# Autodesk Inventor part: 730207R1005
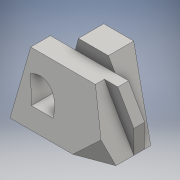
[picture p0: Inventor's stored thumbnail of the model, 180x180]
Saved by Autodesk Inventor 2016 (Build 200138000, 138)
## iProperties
Created: 2023-02
Part Number: 730207R1005
Material: 일반
Document SubType Name: Modeling
Designer: PC-1-18
Density: 1 g/cm^3
Appearance: 기본값
Author: PC-1-18
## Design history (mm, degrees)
sketch "스케치1"
  geometry: L1 (-52.5, -22.5)-(52.5, -22.5); L2 (52.5, -22.5)-(52.5, 22.5); L3 (52.5, 22.5)-(-52.5, 22.5); L4 (-52.5, 22.5)-(-52.5, -22.5); L5 (-52.5, -22.5)-(52.5, 22.5); L6 (52.5, -22.5)-(-52.5, 22.5); 1 further point
  constraints: 12 end point, 2 midpoint, 2 parallel, 1 horizontal, 1 perpendicular
  dimensions: "d0" = 105 distance of L2.end L3.end; "d1" = 45 distance of L1.end L2.end
extrude "돌출1" new body sketch "스케치1" distance "d2" = 57; taper "d3" = 0 deg
sketch "스케치2"
  geometry: L1 (0, 0)-(0, 45) reference; L2 (0, 45)-(-57, 45) reference; L3 (-57, 0)-(-57, 45) reference; L4 (0, 0)-(-57, 0) reference; L5 (0, 0)-(0, 45) reference; L6 (0, 0)-(-57, 23.029); L7 (-57, 0)-(-57, 23.029); L8 (-57, 0)-(-57, 45) reference; L9 (-57, 0)-(0, 0); 1 further point
  constraints: 6 end point, 1 collinear, 1 perpendicular, 1 point on line
  dimensions: "d4" = 68 deg angle of L1 L6
extrude "돌출2" cut sketch "스케치2" stored distance "d5" = 57; taper "d6" = 0 deg
sketch "스케치3"
  geometry: L1 (52.5, -22.5)-(-52.5, -22.5) reference; L2 (52.5, 22.5)-(52.5, -22.5) reference; L3 (-52.5, 22.5)-(52.5, 22.5) reference; L4 (-52.5, -22.5)-(-52.5, 22.5) reference; L5 (-17.5, -22.5)-(-52.5, -9.5); L6 (52.5, -22.5)-(-52.5, -22.5) reference; L7 (-17.5, -22.5)-(-52.5, -22.5); L8 (-52.5, -22.5)-(-52.5, -9.5); L9 (-52.5, -22.5)-(-52.5, 22.5) reference; 1 further point
  constraints: 6 end point, 2 collinear, 2 point on line
  dimensions: "d7" = 13 distance from line of L5.end L1; "d8" = 35 distance from line of L5.start L4
extrude "돌출3" cut sketch "스케치3" stored distance "d9" = 57; taper "d10" = 0 deg
node "작업 평면1"
sketch "스케치4"
  geometry: L1 (-52.5, 0)-(-52.5, 57) reference; L2 (-52.5, 0)-(-19.591, 57); L3 (-17.5, 0)-(-52.5, 32.176) reference; L4 (-52.5, 0)-(-17.5, 0) reference; L5 (-52.5, 32.176)-(-52.5, 0) reference; L6 (52.5, 57)-(-52.5, 57) reference; L7 (-19.591, 57)-(-52.5, 57); L8 (-52.5, 57)-(-52.5, 0); 1 further point
  constraints: 6 end point, 2 collinear, 1 point on line
  dimensions: "d12" = 60 deg angle of L2 L4
extrude "돌출4" cut sketch "스케치4" distance "d13" = 33; taper "d14" = 0 deg
sketch "스케치5"
  geometry: L1 (-52.5, 0)-(-52.5, 57) reference; L2 (-52.5, 26)-(-34.602, 57); L3 (-52.5, 0)-(-17.5, 0) reference; L4 (-40.364, 21.02)-(-19.591, 57) reference; L5 (-19.591, 57)-(-52.5, 57) reference; L6 (-52.5, 57)-(52.5, 57) reference; L7 (-34.602, 57)-(-52.5, 57); L8 (-52.5, 57)-(-52.5, 26); 1 further point
  constraints: 6 end point, 2 collinear, 2 point on line
  dimensions: "d16" = 13 distance between parallel lines of L2 L4; "d17" = 60 deg angle of L3 L2 (derived)
extrude "돌출5" cut sketch "스케치5" stored distance "d18" = 33; taper "d19" = 0 deg
sketch "스케치6"
  geometry: L1 (52.5, 0)-(52.5, 57) reference; L2 (52.5, 0)-(-17.5, 0) reference; L3 (35.5, 17)-(11.5, 17); L4 (35.5, 17)-(45.262, 38.925); A1 r 24 centre (35.5, 17) between (45.262, 38.925) and (11.5, 17); A2 r 24 centre (35.5, 17) between (52.5, 33.941) and (45.262, 38.925); A3 r 24 centre (35.5, 17) between (11.5, 17) and (52.5, 33.941); 1 further point
  constraints: 6 point on circle, 4 end point, 3 centre point, 1 horizontal, 1 point on line
  dimensions: "d20" = 17 distance from line of L1 L3.start; "d21" = 17 distance from line of L2 L3.start; "d22" = 24 radius of A1; "d23" = 114 deg angle of L3 L4
extrude "돌출6" cut sketch "스케치6" stored distance "d24" = 33; taper "d25" = 0 deg
sketch "스케치8"
  geometry: L1 (17, -17)-(41, -17) reference; L2 (17, -17)-(41, -17); L3 (41, -17)-(41, 0); L4 (105, 0)-(70, 0) reference; L5 (41, 0)-(105, 0); L6 (105, 0)-(64.585, -70); L7 (105, 0)-(72.091, -57) reference; L8 (64.585, -70)-(31.201, -70); L9 (7.238, -38.925)-(17, -17) reference; L10 (31.201, -70)-(17, -17); L11 (87.102, -57)-(0, -57) reference; 1 further point
  constraints: 12 end point, 3 collinear, 1 parallel, 1 perpendicular
  dimensions: "d30" = 13 distance between parallel lines of L8 L11; "d31" = 39 deg angle of L9 L10
extrude "돌출7" join sketch "스케치8" distance "d32" = 12; taper "d33" = 0 deg
feature "면 기울기1" dims angle "d34" = 17 deg
node "솔리드1"
node "투영된 루프1"
node "투영된 루프2"
node "투영된 루프3"
other parameters: "d11" = -22.5
